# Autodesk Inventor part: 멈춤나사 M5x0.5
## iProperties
Company: 한국ATC센터
IsCustomPart: 1
Created: 2014-10
Part Number: 멈춤나사 M5x0.5
Material: 강, 연강
Description: 6각 소켓 머리 없는 멈춤 나사
Document SubType Name: Modeling
Standard: KS B 1028
Designer: 한국ATC센터
Standards Organization: KS
Language: ko-KR
Size Designation: 원추점 M5x10
Categories: <MemberInstance><Categories><Category DisplayName="조임쇠" InternalName="e4da775c-781d-43d5-af7c-5136215cf5a6" Mnemonic="FSTN"><Category DisplayName="볼트" InternalN
Density: 7.86 g/cm^3
Mass: 1.16912 g
Surface Area: 1.91683 cm^2
Volume: 0.148743 cm^3
Author: KYOUNG IL JANG
Revision Number: 1
